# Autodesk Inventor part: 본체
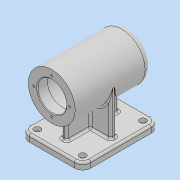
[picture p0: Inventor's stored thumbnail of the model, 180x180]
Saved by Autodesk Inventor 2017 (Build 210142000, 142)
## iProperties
Part Number: 본체
Material: 일반
Document SubType Name: Modeling
Designer: mrc
Density: 1 g/cm^3
Appearance: 기본값
Author: mrc
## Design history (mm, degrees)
sketch "스케치1"
  geometry: L1 (-44, -45)-(44, -45); L2 (56, -33)-(56, 33); L3 (44, 45)-(-44, 45); L4 (-56, 33)-(-56, -33); L5 (-56, -45)-(56, 45); L6 (56, -45)-(-56, 45); C1 r 2.75 at (-44, 33); C2 r 2.75 at (44, 33); C3 r 2.75 at (44, -33); C4 r 2.75 at (-44, -33); A1 r 12 centre (-44, 33) between (-44, 45) and (-56, 33); A2 r 12 centre (44, 33) between (56, 33) and (44, 45); A3 r 12 centre (44, -33) between (44, -45) and (56, -33); A4 r 12 centre (-44, -33) between (-56, -33) and (-44, -45); 1 further point
  constraints: 12 end point, 8 centre point, 8 point on circle, 8 point on line, 8 tangent, 4 coincident, 3 equal radius, 2 midpoint, 2 parallel, 1 horizontal, 1 perpendicular
  dimensions: "d0" = 112 distance of L5.end L6.end; "d1" = 90 distance of L6.end L5.start; "d2" = 12 radius of A1; "d3" = 5.5 diameter of C1; "d4" = 5.5 diameter of C2; "d5" = 5.5 diameter of C3; "d6" = 5.5 diameter of C4
extrude "돌출1" new body sketch "스케치1" distance "d7" = 10; taper "d8" = 0 deg
sketch "스케치3"
  geometry: L1 (33, 0)-(-33, 0) reference; C1 r 34 at (0, 74); 1 further point
  constraints: 1 centre point, 1 vertical alignment
  dimensions: "d9" = 68 diameter of C1; "d10" = 74 distance from line of L1 C1.centre
extrude "돌출2" join sketch "스케치3" stored distance "d11" = 112; taper "d12" = 0 deg
sketch "스케치4"
  geometry: L1 (50, 74)-(-56, 74); L2 (50, 74)-(50, 84.5); L3 (50, 84.5)-(47, 84.5); L4 (47, 84.5)-(47, 90); L5 (47, 90)-(43, 90); L6 (43, 90)-(43, 91.5); L7 (43, 91.5)-(25, 91.5); L8 (25, 91.5)-(25, 95); L9 (25, 95)-(13, 95); L10 (13, 95)-(13, 100); L11 (13, 100)-(-41, 100); L12 (-41, 100)-(-41, 95); L13 (-41, 95)-(-56, 95); L14 (-56, 108)-(-56, 40) reference; L15 (-56, 95)-(-56, 74); 1 further point
  constraints: 28 end point, 11 perpendicular, 1 horizontal, 1 midpoint, 1 point on line, 1 vertical
  dimensions: "d14" = 42 diameter of L13 L1; "d15" = 52 diameter of L11 L1; "d16" = 42 diameter of L9 L1; "d17" = 21 diameter of L3 L1; "d18" = 32 diameter of L5 L1; "d19" = 35 diameter of L7 L1; "d20" = 3 distance between parallel lines of L4 L2; "d21" = 4 distance between parallel lines of L6 L4; "d22" = 18 distance between parallel lines of L8 L6; "d23" = 12 distance between parallel lines of L10 L8; "d24" = 54 distance between parallel lines of L12 L10; "d25" = 15 distance between parallel lines of L14 L12
revolve "회전1" sketch "스케치4" stored, may be unused: angle "d26" = 90 deg
fillet "모깎기1" dims "d27" = 3
fillet "모깎기2" dims "d28" = 3
chamfer "모따기1" distance "d29" = 1; stored, may be unused: second distance "d30" = 2, angle "d31" = 45 deg
fillet "모깎기3" dims "d32" = 10
fillet "모깎기4" dims "d33" = 3
sketch "스케치5"
  geometry: L1 (46, 40)-(-56, 40) reference; L2 (38, 43)-(38, 10); L3 (44, 10)-(-44, 10) reference; L4 (56, 0)-(56, 7) reference; L5 (-56, 0)-(-56, 7) reference; L6 (38, 43)-(-38, 43); L7 (-38, 43)-(-38, 10); L8 (38, 10)-(-38, 10); 1 further point
  constraints: 8 end point, 1 collinear, 1 horizontal, 1 perpendicular, 1 point on line
  dimensions: "d34" = 18 distance between parallel lines of L4 L2; "d36" = 18 distance between parallel lines of L5 L7; "d37" = 3 distance between parallel lines of L1 L6
extrude "돌출3" join sketch "스케치5" stored distance "d38" = 8; taper "d39" = 0 deg
sketch "스케치6"
  geometry: L1 (-34, 52.54)-(-34, 10); L2 (-33, 10)-(33, 10) reference; 1 further point
  constraints: 2 end point, 1 point on line, 1 vertical
  dimensions: "d40" = 34 distance from line of point (0, 0) L1
feature "리브1" sketch "스케치6" dims "d41" = 1, "d42" = 8, "d43" = 0, "d44" = 0, "d45" = 1, "d46" = 1
fillet "모깎기5" dims "d47" = 3
fillet "모깎기6" dims "d48" = 3
fillet "모깎기7" dims "d49" = 3
sketch "스케치7"
  geometry: C1 r 34 at (0, 0) reference; 2 further points
  constraints: 1 horizontal alignment
  dimensions: "d50" = 26 distance of C1.centre point (-26, 0)
hole "구멍1" sketch "스케치7" at (-26, 0) diameter "d51" = 3.242; stored, may be unused: countersink angle "d55" = 90 deg, drill point angle "d57" = 118 deg; dims "d52" = 8, "d53" = 4, "d54" = 2, "d56" = 11
fillet "모깎기8" dims "d61" = 0.3
sketch "스케치8"
  geometry: C1 r 2.75 at (44, -33) reference; C2 r 4.75 at (44, -33); C3 r 2.75 at (-44, -33) reference; C4 r 4.75 at (-44, -33); C5 r 2.75 at (-44, 33) reference; C6 r 4.75 at (-44, 33); C7 r 2.75 at (44, 33) reference; C8 r 4.75 at (44, 33); 1 further point
  constraints: 4 centre point, 4 coincident
  dimensions: "d62" = 9.5 diameter of C2; "d63" = 9.5 diameter of C4; "d64" = 9.5 diameter of C6; "d65" = 9.5 diameter of C8
extrude "돌출4" cut sketch "스케치8" distance "d66" = 5.4; taper "d67" = 0 deg
sketch "스케치9"
  geometry: L1 (100, 0)-(100, 7) reference; 2 further points
  constraints: 1 other
  dimensions: "d68" = 56 distance from line of L1 point (44, 3); "d69" = 3 distance of point (44, 0) point (44, 3)
feature "엠보싱1" sketch "스케치9" dims "d0" = 112, "d1" = 90, "d2" = 12, "d3" = 5.5, "d4" = 5.5, "d5" = 5.5, "d6" = 5.5, "d70" = 0.5, "d71" = 0
node "솔리드1"
mirror "미러1"
pattern_circular "원형 패턴1" dims angle "d59" = 360 deg
